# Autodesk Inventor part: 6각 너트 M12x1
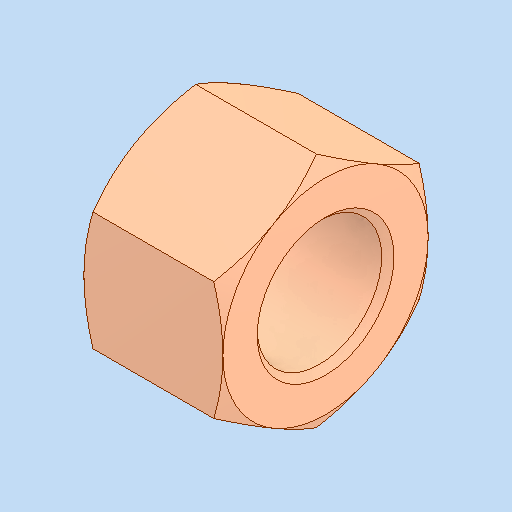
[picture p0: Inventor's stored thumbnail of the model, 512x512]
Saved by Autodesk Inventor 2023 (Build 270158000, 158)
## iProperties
Created: 2026-06
Part Number: 6각 너트 M12x1
Material: 강철, 연강
Description: 6각 너트 및 6각 가는 너트
Document SubType Name: Modeling
Designer: home
Density: 7.85 g/cm^3
Appearance: 기본값
Author: jhkim
Sending System: Autodesk Inventor 2027
Preprocessor: ST-DEVELOPER v20.1
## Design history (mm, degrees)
feature "Solid1"
node "솔리드1"
